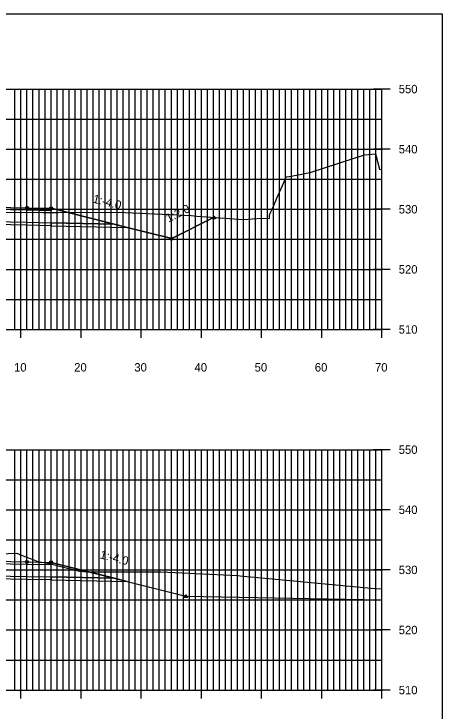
# Model space of a CAD drawing. Extents: x 1509063 to 1512863, y 401160 to 402918.
# Drawn here: x 1512071.6 to 1512142.7, y 402346.1 to 402462.1 of the extents above; entities that cross this region are included whole.
import ezdxf

# ---------------------------------------------------------------- set-up
doc = ezdxf.new("R2010")
doc.units = 0
for name, color, linetype in [('DD_P', 7, 'Continuous'), ('LCUT_P', 7, 'Continuous'), ('NBL1', 7, 'Continuous'), ('PET_P', 7, 'Continuous'), ('PSP_P', 7, 'Continuous'), ('RBS_P', 7, 'Continuous'), ('XAX_P', 7, 'Continuous'), ('XAXTIC_P', 7, 'Continuous'), ('XAXTXT_P_T', 7, 'Continuous'), ('XGL_P', 7, 'Continuous'), ('XSL1_P', 7, 'Continuous'), ('XSL1_P_T', 7, 'Continuous'), ('XSL2_P', 7, 'Continuous'), ('XSL3_P', 7, 'Continuous'), ('XSLOG', 7, 'Continuous')]:
    doc.layers.add(name, color=color, linetype=linetype)

msp = doc.modelspace()

# ---------------------------------------------------------------- linework, layer by layer
at = {"layer": 'DD_P'}
for points in [[(1512077.73, 402429.74), (1512090.41, 402426.57)], [(1512104.83, 402428.24), (1512097.79, 402424.73), (1512090.41, 402426.57)], [(1512077.73, 402370.83), (1512090.41, 402367.66)], [(1512090.41, 402367.66), (1512100.15, 402365.23), (1512132.73, 402364.58)]]:
    msp.add_lwpolyline(points, dxfattribs=at)
for points in [[(1512097.79, 402424.98), (1512098.04, 402424.48), (1512097.54, 402424.48)], [(1512100.15, 402365.48), (1512100.4, 402364.98), (1512099.9, 402364.98)]]:
    msp.add_lwpolyline(points, close=True, dxfattribs=at)
at = {"layer": 'LCUT_P'}
msp.add_lwpolyline([(1512104.83, 402428.49), (1512105.08, 402427.99), (1512104.58, 402427.99)], close=True, dxfattribs=at)
at = {"layer": 'NBL1'}
msp.add_lwpolyline([(1512142.73, 402252.08), (1511822.73, 402252.08), (1511822.73, 402462.08), (1512142.73, 402462.08)], close=True, dxfattribs=at)
at = {"layer": 'PET_P'}
for centre in [(1512073.73, 402429.82), (1512073.73, 402370.91)]:
    msp.add_circle(centre, 0.25, dxfattribs=at)
at = {"layer": 'PSP_P'}
for centre in [(1512077.73, 402429.74), (1512077.73, 402370.83)]:
    msp.add_circle(centre, 0.25, dxfattribs=at)
at = {"layer": 'RBS_P'}
for points in [[(1512062.72, 402429.63), (1512062.72, 402427.63), (1512073.73, 402427.41), (1512077.73, 402427.33), (1512088.24, 402427.12), (1512077.73, 402429.74), (1512077.73, 402429.33), (1512073.73, 402429.41)], [(1512062.72, 402370.72), (1512062.72, 402368.72), (1512073.73, 402368.5), (1512077.73, 402368.42), (1512088.24, 402368.21), (1512077.73, 402370.83), (1512077.73, 402370.42), (1512073.73, 402370.5)]]:
    msp.add_lwpolyline(points, close=True, dxfattribs=at)
for points in [[(1512077.73, 402429.74), (1512077.73, 402429.99), (1512077.73, 402429.74), (1512077.48, 402429.74), (1512077.73, 402429.74), (1512077.73, 402429.49), (1512077.73, 402429.74), (1512077.98, 402429.74)], [(1512077.73, 402370.83), (1512077.73, 402371.08), (1512077.73, 402370.83), (1512077.48, 402370.83), (1512077.73, 402370.83), (1512077.73, 402370.58), (1512077.73, 402370.83), (1512077.98, 402370.83)]]:
    msp.add_lwpolyline(points, dxfattribs=at)
at = {"layer": 'XAX_P'}
for p, q in [((1512132.73, 402409.58), (1512132.73, 402449.58)), ((1511992.73, 402409.58), (1512132.73, 402409.58)), ((1512132.73, 402349.58), (1512132.73, 402389.58)), ((1511992.73, 402349.58), (1512132.73, 402349.58))]:
    msp.add_line(p, q, dxfattribs=at)
at = {"layer": 'XAXTIC_P'}
for p, q in [((1512134.13, 402449.58), (1512131.33, 402449.58)), ((1512134.13, 402439.58), (1512131.33, 402439.58)), ((1512134.13, 402429.58), (1512131.33, 402429.58)), ((1512134.13, 402419.58), (1512131.33, 402419.58)), ((1512072.73, 402408.18), (1512072.73, 402410.98)), ((1512082.73, 402408.18), (1512082.73, 402410.98)), ((1512092.73, 402408.18), (1512092.73, 402410.98)), ((1512102.73, 402408.18), (1512102.73, 402410.98)), ((1512112.73, 402408.18), (1512112.73, 402410.98)), ((1512122.73, 402408.18), (1512122.73, 402410.98)), ((1512132.73, 402408.18), (1512132.73, 402410.98)), ((1512134.13, 402409.58), (1512131.33, 402409.58)), ((1512134.13, 402389.58), (1512131.33, 402389.58)), ((1512134.13, 402379.58), (1512131.33, 402379.58)), ((1512134.13, 402369.58), (1512131.33, 402369.58)), ((1512134.13, 402359.58), (1512131.33, 402359.58)), ((1512072.73, 402348.18), (1512072.73, 402350.98)), ((1512082.73, 402348.18), (1512082.73, 402350.98)), ((1512092.73, 402348.18), (1512092.73, 402350.98)), ((1512102.73, 402348.18), (1512102.73, 402350.98)), ((1512112.73, 402348.18), (1512112.73, 402350.98)), ((1512122.73, 402348.18), (1512122.73, 402350.98)), ((1512132.73, 402348.18), (1512132.73, 402350.98)), ((1512134.13, 402349.58), (1512131.33, 402349.58))]:
    msp.add_line(p, q, dxfattribs=at)
at = {"layer": 'XGL_P'}
for p, q in [((1511992.73, 402449.58), (1512132.73, 402449.58)), ((1512071.73, 402409.58), (1512071.73, 402449.58)), ((1512072.73, 402409.58), (1512072.73, 402449.58)), ((1512073.73, 402409.58), (1512073.73, 402449.58)), ((1512074.73, 402409.58), (1512074.73, 402449.58)), ((1512075.73, 402409.58), (1512075.73, 402449.58)), ((1512076.73, 402409.58), (1512076.73, 402449.58)), ((1512077.73, 402409.58), (1512077.73, 402449.58)), ((1512078.73, 402409.58), (1512078.73, 402449.58)), ((1512079.73, 402409.58), (1512079.73, 402449.58)), ((1512080.73, 402409.58), (1512080.73, 402449.58)), ((1512081.73, 402409.58), (1512081.73, 402449.58)), ((1512082.73, 402409.58), (1512082.73, 402449.58)), ((1512083.73, 402409.58), (1512083.73, 402449.58)), ((1512084.73, 402409.58), (1512084.73, 402449.58)), ((1512085.73, 402409.58), (1512085.73, 402449.58)), ((1512086.73, 402409.58), (1512086.73, 402449.58)), ((1512087.73, 402409.58), (1512087.73, 402449.58)), ((1512088.73, 402409.58), (1512088.73, 402449.58)), ((1512089.73, 402409.58), (1512089.73, 402449.58)), ((1512090.73, 402409.58), (1512090.73, 402449.58)), ((1512091.73, 402409.58), (1512091.73, 402449.58)), ((1512092.73, 402409.58), (1512092.73, 402449.58)), ((1512093.73, 402409.58), (1512093.73, 402449.58)), ((1512094.73, 402409.58), (1512094.73, 402449.58)), ((1512095.73, 402409.58), (1512095.73, 402449.58)), ((1512096.73, 402409.58), (1512096.73, 402449.58)), ((1512097.73, 402409.58), (1512097.73, 402449.58)), ((1512098.73, 402409.58), (1512098.73, 402449.58)), ((1512099.73, 402409.58), (1512099.73, 402449.58)), ((1512100.73, 402409.58), (1512100.73, 402449.58)), ((1512101.73, 402409.58), (1512101.73, 402449.58)), ((1512102.73, 402409.58), (1512102.73, 402449.58)), ((1512103.73, 402409.58), (1512103.73, 402449.58)), ((1512104.73, 402409.58), (1512104.73, 402449.58)), ((1512105.73, 402409.58), (1512105.73, 402449.58)), ((1512106.73, 402409.58), (1512106.73, 402449.58)), ((1512107.73, 402409.58), (1512107.73, 402449.58)), ((1512108.73, 402409.58), (1512108.73, 402449.58)), ((1512109.73, 402409.58), (1512109.73, 402449.58)), ((1512110.73, 402409.58), (1512110.73, 402449.58)), ((1512111.73, 402409.58), (1512111.73, 402449.58)), ((1512112.73, 402409.58), (1512112.73, 402449.58)), ((1512113.73, 402409.58), (1512113.73, 402449.58)), ((1512114.73, 402409.58), (1512114.73, 402449.58)), ((1512115.73, 402409.58), (1512115.73, 402449.58)), ((1512116.73, 402409.58), (1512116.73, 402449.58)), ((1512117.73, 402409.58), (1512117.73, 402449.58)), ((1512118.73, 402409.58), (1512118.73, 402449.58)), ((1512119.73, 402409.58), (1512119.73, 402449.58)), ((1512120.73, 402409.58), (1512120.73, 402449.58)), ((1512121.73, 402409.58), (1512121.73, 402449.58)), ((1512122.73, 402409.58), (1512122.73, 402449.58)), ((1512123.73, 402409.58), (1512123.73, 402449.58)), ((1512124.73, 402409.58), (1512124.73, 402449.58)), ((1512125.73, 402409.58), (1512125.73, 402449.58)), ((1512126.73, 402409.58), (1512126.73, 402449.58)), ((1512127.73, 402409.58), (1512127.73, 402449.58)), ((1512128.73, 402409.58), (1512128.73, 402449.58)), ((1512129.73, 402409.58), (1512129.73, 402449.58)), ((1512130.73, 402409.58), (1512130.73, 402449.58)), ((1512131.73, 402409.58), (1512131.73, 402449.58)), ((1512132.73, 402409.58), (1512132.73, 402449.58)), ((1511992.73, 402444.58), (1512132.73, 402444.58)), ((1511992.73, 402439.58), (1512132.73, 402439.58)), ((1511992.73, 402434.58), (1512132.73, 402434.58)), ((1511992.73, 402429.58), (1512132.73, 402429.58)), ((1511992.73, 402424.58), (1512132.73, 402424.58)), ((1511992.73, 402419.58), (1512132.73, 402419.58)), ((1511992.73, 402414.58), (1512132.73, 402414.58)), ((1511992.73, 402409.58), (1512132.73, 402409.58)), ((1511992.73, 402389.58), (1512132.73, 402389.58)), ((1512071.73, 402349.58), (1512071.73, 402389.58)), ((1512072.73, 402349.58), (1512072.73, 402389.58)), ((1512073.73, 402349.58), (1512073.73, 402389.58)), ((1512074.73, 402349.58), (1512074.73, 402389.58)), ((1512075.73, 402349.58), (1512075.73, 402389.58)), ((1512076.73, 402349.58), (1512076.73, 402389.58)), ((1512077.73, 402349.58), (1512077.73, 402389.58)), ((1512078.73, 402349.58), (1512078.73, 402389.58)), ((1512079.73, 402349.58), (1512079.73, 402389.58)), ((1512080.73, 402349.58), (1512080.73, 402389.58)), ((1512081.73, 402349.58), (1512081.73, 402389.58)), ((1512082.73, 402349.58), (1512082.73, 402389.58)), ((1512083.73, 402349.58), (1512083.73, 402389.58)), ((1512084.73, 402349.58), (1512084.73, 402389.58)), ((1512085.73, 402349.58), (1512085.73, 402389.58)), ((1512086.73, 402349.58), (1512086.73, 402389.58)), ((1512087.73, 402349.58), (1512087.73, 402389.58)), ((1512088.73, 402349.58), (1512088.73, 402389.58)), ((1512089.73, 402349.58), (1512089.73, 402389.58)), ((1512090.73, 402349.58), (1512090.73, 402389.58)), ((1512091.73, 402349.58), (1512091.73, 402389.58)), ((1512092.73, 402349.58), (1512092.73, 402389.58)), ((1512093.73, 402349.58), (1512093.73, 402389.58)), ((1512094.73, 402349.58), (1512094.73, 402389.58)), ((1512095.73, 402349.58), (1512095.73, 402389.58)), ((1512096.73, 402349.58), (1512096.73, 402389.58)), ((1512097.73, 402349.58), (1512097.73, 402389.58)), ((1512098.73, 402349.58), (1512098.73, 402389.58)), ((1512099.73, 402349.58), (1512099.73, 402389.58)), ((1512100.73, 402349.58), (1512100.73, 402389.58)), ((1512101.73, 402349.58), (1512101.73, 402389.58)), ((1512102.73, 402349.58), (1512102.73, 402389.58)), ((1512103.73, 402349.58), (1512103.73, 402389.58)), ((1512104.73, 402349.58), (1512104.73, 402389.58)), ((1512105.73, 402349.58), (1512105.73, 402389.58)), ((1512106.73, 402349.58), (1512106.73, 402389.58)), ((1512107.73, 402349.58), (1512107.73, 402389.58)), ((1512108.73, 402349.58), (1512108.73, 402389.58)), ((1512109.73, 402349.58), (1512109.73, 402389.58)), ((1512110.73, 402349.58), (1512110.73, 402389.58)), ((1512111.73, 402349.58), (1512111.73, 402389.58)), ((1512112.73, 402349.58), (1512112.73, 402389.58)), ((1512113.73, 402349.58), (1512113.73, 402389.58)), ((1512114.73, 402349.58), (1512114.73, 402389.58)), ((1512115.73, 402349.58), (1512115.73, 402389.58)), ((1512116.73, 402349.58), (1512116.73, 402389.58)), ((1512117.73, 402349.58), (1512117.73, 402389.58)), ((1512118.73, 402349.58), (1512118.73, 402389.58)), ((1512119.73, 402349.58), (1512119.73, 402389.58)), ((1512120.73, 402349.58), (1512120.73, 402389.58)), ((1512121.73, 402349.58), (1512121.73, 402389.58)), ((1512122.73, 402349.58), (1512122.73, 402389.58)), ((1512123.73, 402349.58), (1512123.73, 402389.58)), ((1512124.73, 402349.58), (1512124.73, 402389.58)), ((1512125.73, 402349.58), (1512125.73, 402389.58)), ((1512126.73, 402349.58), (1512126.73, 402389.58)), ((1512127.73, 402349.58), (1512127.73, 402389.58)), ((1512128.73, 402349.58), (1512128.73, 402389.58)), ((1512129.73, 402349.58), (1512129.73, 402389.58)), ((1512130.73, 402349.58), (1512130.73, 402389.58)), ((1512131.73, 402349.58), (1512131.73, 402389.58)), ((1512132.73, 402349.58), (1512132.73, 402389.58)), ((1511992.73, 402384.58), (1512132.73, 402384.58)), ((1511992.73, 402379.58), (1512132.73, 402379.58)), ((1511992.73, 402374.58), (1512132.73, 402374.58)), ((1511992.73, 402369.58), (1512132.73, 402369.58)), ((1511992.73, 402364.58), (1512132.73, 402364.58)), ((1511992.73, 402359.58), (1512132.73, 402359.58)), ((1511992.73, 402354.58), (1512132.73, 402354.58)), ((1511992.73, 402349.58), (1512132.73, 402349.58))]:
    msp.add_line(p, q, dxfattribs=at)
at = {"layer": 'XSL1_P'}
for points in [[(1512020.05, 402431.07), (1512030.2, 402426), (1512032.24, 402427.02), (1512038.65, 402430.22), (1512042.23, 402430.44), (1512047.23, 402430.34), (1512047.63, 402430.33), (1512047.73, 402429.74), (1512051.73, 402429.82), (1512062.73, 402430.04), (1512073.73, 402429.82), (1512077.73, 402429.74), (1512088.24, 402427.12), (1512090.41, 402426.57), (1512097.79, 402424.73), (1512104.83, 402428.24)], [(1512019.12, 402372.62), (1512030.2, 402367.08), (1512032.24, 402368.11), (1512038.65, 402371.31), (1512042.23, 402371.52), (1512047.23, 402371.42), (1512047.63, 402371.42), (1512047.73, 402370.83), (1512051.73, 402370.91), (1512062.73, 402371.13), (1512073.73, 402370.91), (1512077.73, 402370.83), (1512088.24, 402368.21), (1512090.41, 402367.66), (1512100.15, 402365.23)]]:
    msp.add_lwpolyline(points, dxfattribs=at)
at = {"layer": 'XSL2_P'}
for points in [[(1512073.73, 402426.91), (1512062.72, 402427.13), (1512051.73, 402426.91), (1512047.8, 402426.83), (1512047.8, 402427.33), (1512051.73, 402427.41), (1512062.72, 402427.63), (1512073.73, 402427.41), (1512077.73, 402427.33), (1512077.73, 402426.83)], [(1512077.73, 402427.33), (1512077.73, 402426.83), (1512090.41, 402426.57), (1512088.24, 402427.12)], [(1512073.73, 402368), (1512062.72, 402368.22), (1512051.73, 402368), (1512047.8, 402367.92), (1512047.8, 402368.42), (1512051.73, 402368.5), (1512062.72, 402368.72), (1512073.73, 402368.5), (1512077.73, 402368.42), (1512077.73, 402367.92)], [(1512077.73, 402368.42), (1512077.73, 402367.92), (1512090.41, 402367.66), (1512088.24, 402368.21)]]:
    msp.add_lwpolyline(points, close=True, dxfattribs=at)
for points in [[(1512077.73, 402427.33), (1512088.24, 402427.12)], [(1512077.73, 402368.42), (1512088.24, 402368.21)]]:
    msp.add_lwpolyline(points, dxfattribs=at)
at = {"layer": 'XSL3_P'}
for points in [[(1512051.73, 402429.41), (1512047.8, 402429.33), (1512047.73, 402429.74), (1512051.73, 402429.82), (1512062.72, 402430.04), (1512073.73, 402429.82), (1512077.73, 402429.74), (1512077.73, 402429.33), (1512073.73, 402429.41), (1512062.72, 402429.63)], [(1512051.73, 402370.5), (1512047.8, 402370.42), (1512047.73, 402370.83), (1512051.73, 402370.91), (1512062.72, 402371.13), (1512073.73, 402370.91), (1512077.73, 402370.83), (1512077.73, 402370.42), (1512073.73, 402370.5), (1512062.72, 402370.72)]]:
    msp.add_lwpolyline(points, close=True, dxfattribs=at)
at = {"layer": 'XSLOG'}
for points in [[(1512068.97, 402429.07), (1512076.34, 402429.03), (1512078.91, 402429.04), (1512088.81, 402429.09), (1512096.2, 402428.77), (1512101.05, 402428.57), (1512101.95, 402428.45), (1512109.73, 402427.89), (1512112.69, 402428.1), (1512114.05, 402428.07), (1512114.06, 402428.64), (1512114.16, 402428.86), (1512114.29, 402429.15), (1512114.47, 402429.58), (1512114.76, 402430.23), (1512115.27, 402431.4), (1512116.42, 402434.02), (1512116.83, 402434.95), (1512117.31, 402435.04), (1512119.4, 402435.43), (1512120.98, 402435.73), (1512129.85, 402438.62), (1512131.65, 402438.82), (1512132.34, 402436.27), (1512132.73, 402436.21)], [(1512067.73, 402372.17), (1512072.06, 402372.35), (1512072.82, 402372.04), (1512073.66, 402371.71), (1512074.6, 402371.34), (1512075.66, 402370.92), (1512076.21, 402370.89), (1512077.42, 402370.63), (1512080.24, 402369.93), (1512081.4, 402369.64), (1512082.04, 402369.48), (1512082.44, 402369.38), (1512083.73, 402369.27), (1512091.78, 402369.25), (1512095.98, 402369.23), (1512101.83, 402368.96), (1512108.66, 402368.65), (1512109.67, 402368.56), (1512112.1, 402368.33), (1512131.55, 402366.48), (1512132.73, 402366.41)]]:
    msp.add_lwpolyline(points, dxfattribs=at)

# ---------------------------------------------------------------- texts
at = {"layer": 'XAXTXT_P_T'}
for s, p in [('550', (1512135.53, 402448.88)), ('540', (1512135.53, 402438.88)), ('530', (1512135.53, 402428.88)), ('520', (1512135.53, 402418.88)), ('510', (1512135.53, 402408.88)), ('10', (1512071.58, 402402.58)), ('20', (1512081.58, 402402.58)), ('30', (1512091.58, 402402.58)), ('40', (1512101.58, 402402.58)), ('50', (1512111.58, 402402.58)), ('60', (1512121.58, 402402.58)), ('70', (1512131.58, 402402.58)), ('550', (1512135.53, 402388.88)), ('540', (1512135.53, 402378.88)), ('530', (1512135.53, 402368.88)), ('520', (1512135.53, 402358.88)), ('510', (1512135.53, 402348.88))]:
    msp.add_text(s, height=1.4, dxfattribs=at).set_placement(p)
at = {"layer": 'XSL1_P_T'}
for s, rotation, p in [('1:-4.0', 345.9638, (1512084.58, 402430.71)), ('1:-4.0', 345.9638, (1512084.58, 402430.71)), ('1:-4.0', 345.9638, (1512084.58, 402430.71)), ('1:2.0', 26.5651, (1512097.25, 402427.36)), ('1:2.0', 26.5651, (1512097.25, 402427.36)), ('1:2.0', 26.5651, (1512097.25, 402427.36)), ('1:-4.0', 345.9638, (1512085.76, 402371.51)), ('1:-4.0', 345.9638, (1512085.76, 402371.51)), ('1:-4.0', 345.9638, (1512085.76, 402371.51))]:
    msp.add_text(s, height=1.4, rotation=rotation, dxfattribs=at).set_placement(p)

doc.saveas('drawing.dxf')
